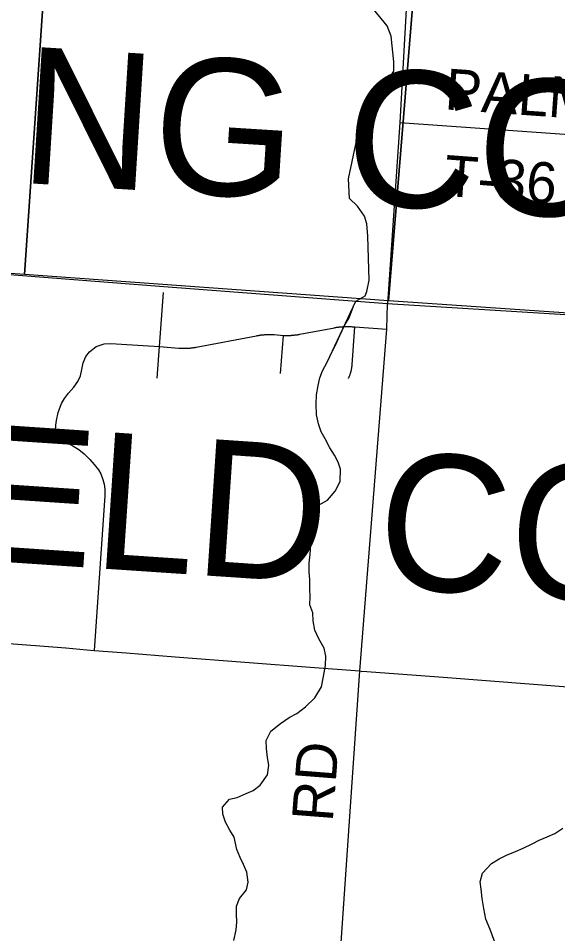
# Model space of a CAD drawing. Extents: x 0 to 34, y 0 to 26.1.
# Drawn here: x 28.767 to 29.516, y 17.037 to 18.306 of the extents above; entities that cross this region are included whole.
import ezdxf

# ---------------------------------------------------------------- set-up
doc = ezdxf.new("R2010")
doc.units = 0
for name, color, linetype in [('GM_X_County', 7, 'Continuous'), ('GM_X_County_Text', 7, 'Continuous'), ('GM_X_Minor_River', 7, 'Continuous'), ('GM_X_Section', 7, 'Continuous'), ('GM_X_State_Route', 7, 'Continuous'), ('GM_X_Township_Road', 7, 'Continuous'), ('GM_X_Township_Road_Text', 7, 'Continuous')]:
    doc.layers.add(name, color=color, linetype=linetype)

msp = doc.modelspace()

# ---------------------------------------------------------------- linework, layer by layer
at = {"layer": 'GM_X_County'}
msp.add_lwpolyline([(27.2717, 18.0608), (27.381, 18.0532), (27.4688, 18.0465), (27.5252, 18.0428), (28.0021, 18.0085), (28.6835, 17.9564), (28.9692, 17.9346), (29.2794, 17.911), (29.6089, 17.8905)], dxfattribs=at)
at = {"layer": 'GM_X_Minor_River'}
for points in [[(29.2357, 17.9139), (29.2486, 17.9215), (29.2512, 17.9276), (29.2543, 17.9431), (29.2525, 18.0043), (29.2511, 18.0213), (29.248, 18.032), (29.2379, 18.0457), (29.2269, 18.0567), (29.2258, 18.0837), (29.2377, 18.1406), (29.248, 18.1747), (29.2575, 18.1948), (29.2704, 18.2142), (29.2852, 18.2282), (29.2886, 18.2331), (29.2886, 18.2396), (29.2883, 18.246), (29.2849, 18.2817), (29.2793, 18.2958), (29.2562, 18.3243), (29.24, 18.3502), (29.2336, 18.3566)], [(29.0663, 17.0274), (29.0695, 17.0421), (29.0704, 17.0527), (29.0701, 17.0641), (29.0703, 17.0751), (29.0742, 17.0854), (29.0841, 17.0974), (29.0862, 17.1084), (29.0844, 17.1221), (29.08, 17.1327), (29.0752, 17.1423), (29.0707, 17.1537), (29.0671, 17.1705), (29.0608, 17.1804), (29.0549, 17.1915), (29.0512, 17.2025), (29.0505, 17.2124), (29.0605, 17.2233), (29.0711, 17.2258), (29.0837, 17.231), (29.0932, 17.2355), (29.1028, 17.2426), (29.1131, 17.2569), (29.1152, 17.2705), (29.1134, 17.2812), (29.1116, 17.2937), (29.1114, 17.3048), (29.1176, 17.3176), (29.1313, 17.3285), (29.1432, 17.3367), (29.1538, 17.3423), (29.1657, 17.3513), (29.1787, 17.364), (29.1879, 17.3791), (29.1911, 17.3935), (29.1939, 17.4087), (29.1941, 17.4216), (29.1916, 17.4326), (29.1845, 17.4456), (29.1789, 17.4578), (29.1764, 17.4707), (29.1762, 17.4817), (29.1718, 17.4928), (29.1722, 17.5038), (29.172, 17.5152), (29.1718, 17.5281), (29.1711, 17.5384), (29.1712, 17.5509), (29.1725, 17.5634), (29.1734, 17.5755), (29.1743, 17.5884), (29.1748, 17.601), (29.1757, 17.6104), (29.1773, 17.621), (29.1839, 17.6312), (29.1964, 17.6383), (29.2072, 17.6507), (29.2138, 17.6639), (29.2147, 17.681), (29.2114, 17.6909), (29.2062, 17.7005), (29.1999, 17.7108), (29.1932, 17.723), (29.1876, 17.7329), (29.1839, 17.744), (29.181, 17.7565), (29.1808, 17.771), (29.1813, 17.7842), (29.1834, 17.7971), (29.1858, 17.8077), (29.1893, 17.8176), (29.1958, 17.8297), (29.2357, 17.9139)], [(29.2028, 17.8444), (29.2082, 17.8542), (29.2137, 17.8663), (29.2206, 17.8814), (29.2264, 17.8912), (29.2323, 17.9056)], [(29.4288, 17.0251), (29.4222, 17.0426), (29.4163, 17.0567), (29.4134, 17.0716), (29.4113, 17.0856), (29.4096, 17.0986), (29.4085, 17.1088), (29.4117, 17.1209), (29.424, 17.1341), (29.4346, 17.1404), (29.4449, 17.1457), (29.4575, 17.1508), (29.4678, 17.1553), (29.4803, 17.1616), (29.4902, 17.1664), (29.5013, 17.1713), (29.5119, 17.1757), (29.523, 17.1832)]]:
    msp.add_lwpolyline(points, dxfattribs=at)
at = {"layer": 'GM_X_Section'}
for points in [[(28.8173, 18.5533), (28.776, 17.9511), (28.2704, 17.9878), (28.3147, 18.5533)], [(29.3334, 18.5533), (29.2811, 17.9144), (28.776, 17.9511), (28.8173, 18.5533)], [(29.825, 18.5533), (29.7809, 17.8804), (29.2811, 17.9144), (29.3334, 18.5533)]]:
    msp.add_lwpolyline(points, dxfattribs=at)
at = {"layer": 'GM_X_State_Route'}
for p, q in [((29.1786, 17.406), (29.2414, 17.4013)), ((29.2414, 17.4013), (29.2434, 17.4011)), ((29.2434, 17.4011), (29.2512, 17.4005))]:
    msp.add_line(p, q, dxfattribs=at)
for points in [[(28.7428, 17.4404), (28.8335, 17.4331), (28.8624, 17.4306)], [(28.8624, 17.4306), (28.8724, 17.4297), (28.917, 17.4261), (28.9851, 17.4206), (29.1786, 17.406)], [(29.2512, 17.4005), (29.3571, 17.3924), (29.6018, 17.3736), (29.7502, 17.3618), (29.841, 17.3569), (30.0155, 17.3502), (30.1955, 17.3437), (30.3167, 17.3357)]]:
    msp.add_lwpolyline(points, dxfattribs=at)
at = {"layer": 'GM_X_Township_Road'}
for p, q in [((29.3107, 18.4123), (29.297, 18.1618)), ((29.297, 18.1618), (29.2796, 17.9104)), ((29.2344, 17.8784), (29.2787, 17.8752)), ((29.1313, 17.8138), (29.1352, 17.8667))]:
    msp.add_line(p, q, dxfattribs=at)
for points in [[(29.297, 18.1618), (29.7996, 18.1265)], [(28.96, 17.8075), (28.9632, 17.851), (28.9688, 17.9261)], [(29.2414, 17.4013), (29.2787, 17.8752), (29.2796, 17.9104)], [(29.1352, 17.8667), (29.136, 17.8667), (29.1367, 17.8666), (29.1375, 17.8666), (29.1383, 17.8666), (29.139, 17.8666), (29.1398, 17.8666), (29.1405, 17.8666), (29.1413, 17.8666), (29.142, 17.8666), (29.1428, 17.8666), (29.1436, 17.8666), (29.1443, 17.8666), (29.1451, 17.8667), (29.1458, 17.8667), (29.1466, 17.8668), (29.1473, 17.8668), (29.1481, 17.8669), (29.1489, 17.8669), (29.1496, 17.867), (29.1504, 17.8671), (29.1511, 17.8672), (29.1519, 17.8672), (29.1526, 17.8673), (29.1534, 17.8674), (29.1541, 17.8675), (29.1549, 17.8676), (29.1556, 17.8678), (29.1564, 17.8679), (29.1571, 17.868), (29.1582, 17.8682), (29.206, 17.8773), (29.2067, 17.8774), (29.2075, 17.8776), (29.2082, 17.8777), (29.209, 17.8778), (29.2097, 17.8779), (29.2105, 17.878), (29.2112, 17.8781), (29.212, 17.8782), (29.2127, 17.8783), (29.2135, 17.8784), (29.2142, 17.8785), (29.215, 17.8786), (29.2157, 17.8786), (29.2165, 17.8787), (29.2173, 17.8787), (29.218, 17.8788), (29.2188, 17.8788), (29.2195, 17.8789), (29.2203, 17.8789), (29.221, 17.8789), (29.2218, 17.8789), (29.2226, 17.879), (29.2233, 17.879), (29.2241, 17.879), (29.2248, 17.879), (29.2256, 17.8789), (29.2263, 17.8789), (29.2271, 17.8789), (29.2279, 17.8789), (29.2286, 17.8788), (29.2294, 17.8788), (29.2305, 17.8787), (29.2344, 17.8784)], [(29.2255, 17.8068), (29.2258, 17.8074), (29.2261, 17.8081), (29.2264, 17.8088), (29.2267, 17.8095), (29.227, 17.8102), (29.2273, 17.8109), (29.2275, 17.8116), (29.2278, 17.8123), (29.228, 17.813), (29.2283, 17.8137), (29.2285, 17.8145), (29.2287, 17.8152), (29.2289, 17.8159), (29.2291, 17.8167), (29.2293, 17.8174), (29.2295, 17.8181), (29.2296, 17.8189), (29.2298, 17.8196), (29.2299, 17.8203), (29.2301, 17.8211), (29.2302, 17.8218), (29.2303, 17.8226), (29.2304, 17.8233), (29.2305, 17.8241), (29.2306, 17.8249), (29.2306, 17.8256), (29.2344, 17.8784)], [(28.9632, 17.851), (28.9901, 17.849), (28.9909, 17.8489), (28.9916, 17.8489), (28.9924, 17.8488), (28.9932, 17.8488), (28.9939, 17.8488), (28.9947, 17.8487), (28.9954, 17.8487), (28.9962, 17.8487), (28.9969, 17.8487), (28.9977, 17.8487), (28.9985, 17.8487), (28.9992, 17.8487), (29, 17.8488), (29.0007, 17.8488), (29.0015, 17.8488), (29.0022, 17.8488), (29.003, 17.8489), (29.0038, 17.8489), (29.0045, 17.849), (29.0053, 17.8491), (29.006, 17.8491), (29.0068, 17.8492), (29.0075, 17.8493), (29.0083, 17.8494), (29.009, 17.8495), (29.0098, 17.8496), (29.0105, 17.8497), (29.0113, 17.8498), (29.012, 17.8499), (29.0128, 17.85), (29.0135, 17.8501), (29.0143, 17.8503), (29.098, 17.8662), (29.0988, 17.8663), (29.0995, 17.8665), (29.1003, 17.8666), (29.101, 17.8667), (29.1018, 17.8668), (29.1025, 17.867), (29.1033, 17.8671), (29.104, 17.8672), (29.1048, 17.8672), (29.1055, 17.8673), (29.1063, 17.8674), (29.107, 17.8675), (29.1078, 17.8675), (29.1086, 17.8676), (29.1093, 17.8677), (29.1101, 17.8677), (29.1108, 17.8678), (29.1116, 17.8678), (29.1123, 17.8678), (29.1131, 17.8678), (29.1138, 17.8679), (29.1146, 17.8679), (29.1154, 17.8679), (29.1161, 17.8679), (29.1169, 17.8679), (29.1176, 17.8679), (29.1184, 17.8678), (29.1191, 17.8678), (29.1199, 17.8678), (29.1207, 17.8678), (29.1214, 17.8677), (29.1222, 17.8677), (29.1352, 17.8667)], [(28.8181, 17.7233), (28.819, 17.7339), (28.8196, 17.7419), (28.8202, 17.7484), (28.8227, 17.7598), (28.8275, 17.772), (28.8316, 17.7793), (28.8368, 17.7863), (28.8444, 17.7946), (28.8501, 17.8026), (28.8537, 17.8107), (28.8557, 17.8195), (28.8573, 17.8287), (28.8612, 17.8373), (28.8661, 17.8439), (28.8753, 17.851), (28.8863, 17.855), (28.8959, 17.8556), (28.9106, 17.8546), (28.9632, 17.851)], [(28.7656, 17.7284), (28.7722, 17.7282), (28.7862, 17.727), (28.8069, 17.7253), (28.8139, 17.7242), (28.8181, 17.7233), (28.8258, 17.7212), (28.8351, 17.7175), (28.8429, 17.7136), (28.8512, 17.7083), (28.8586, 17.7024), (28.8668, 17.6943), (28.8727, 17.6874), (28.8784, 17.6801), (28.8817, 17.6744), (28.8848, 17.6667), (28.8865, 17.6604), (28.8875, 17.6535), (28.8874, 17.6442), (28.8724, 17.4297)], [(29.186, 16.5425), (29.2021, 16.8295), (29.2414, 17.4013)]]:
    msp.add_lwpolyline(points, dxfattribs=at)

# ---------------------------------------------------------------- texts
at = {"layer": 'GM_X_County_Text'}
for s, rotation, p in [('LICKING COUNTY', 356.3996, (28.1352, 18.1183)), ('FAIRFIELD COUNTY', 356.1646, (27.8997, 17.6092))]:
    msp.add_text(s, height=0.189394, rotation=rotation, dxfattribs=at).set_placement(p)
at = {"layer": 'GM_X_Township_Road_Text'}
for s, rotation, p in [('PALMER', 355.9261, (29.3582, 18.1802)), ('T-36', 355.737, (29.3569, 18.0603)), ('RD', 85.564, (29.2036, 17.1911))]:
    msp.add_text(s, height=0.05682, rotation=rotation, dxfattribs=at).set_placement(p)

doc.saveas('drawing.dxf')
